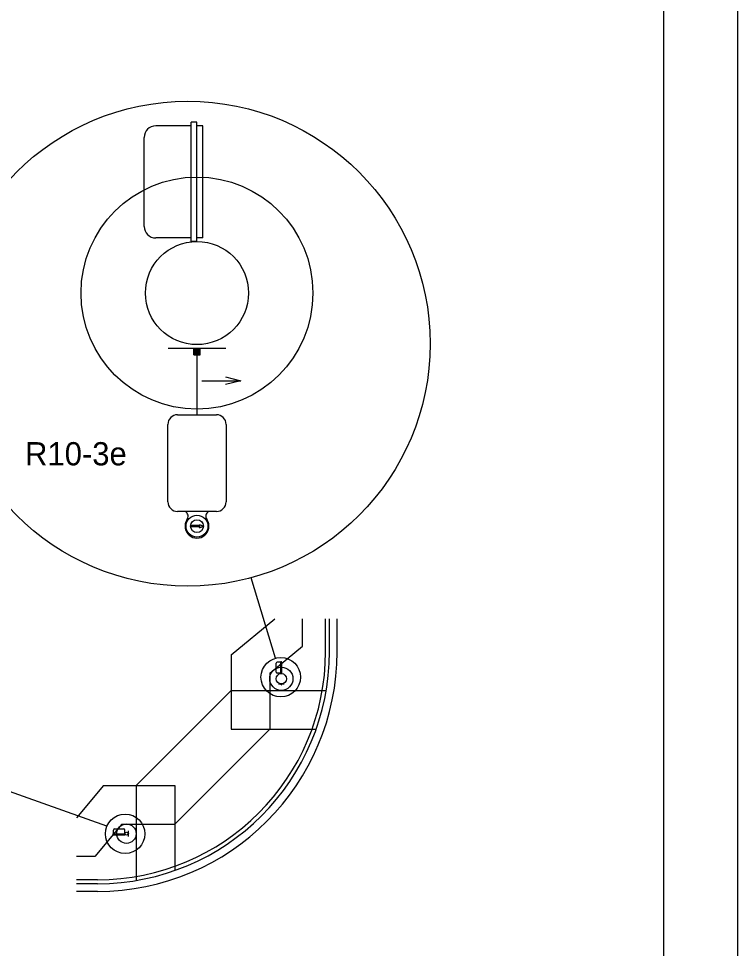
# Model space of a CAD drawing. Extents: x 1369885 to 1370886, y 379976 to 380616.
# Drawn here: x 1370746 to 1370885.5, y 380081.9 to 380262.3 of the extents above; entities that cross this region are included whole.
import ezdxf

# ---------------------------------------------------------------- set-up
doc = ezdxf.new("R2010")
doc.units = 0
for name, color, linetype in [('R_Border', 7, 'Continuous'), ('R_No Plot', 7, 'Continuous'), ('T_Drafting', 7, 'Continuous')]:
    doc.layers.add(name, color=color, linetype=linetype)

msp = doc.modelspace()

# ---------------------------------------------------------------- linework, layer by layer
at = {"layer": 'R_Border'}
msp.add_line((1370871.25, 379987.52), (1370871.25, 380603.9), dxfattribs=at)
at = {"layer": 'R_No Plot'}
msp.add_lwpolyline([(1369885.49, 380615.59), (1370885.51, 380615.59), (1370885.51, 379975.58), (1369885.49, 379975.58)], close=True, dxfattribs=at)
at = {"layer": 'T_Drafting'}
for p, q in [((1370779.52, 380219.04), (1370779.52, 380242.16)), ((1370780.64, 380242.16), (1370779.52, 380242.16)), ((1370780.64, 380219.04), (1370780.64, 380242.16)), ((1370779.52, 380241.48), (1370772.64, 380241.48)), ((1370781.77, 380241.48), (1370780.64, 380241.48)), ((1370781.77, 380219.73), (1370781.77, 380241.48)), ((1370770.39, 380221.98), (1370770.39, 380239.23)), ((1370779.52, 380219.73), (1370772.64, 380219.73)), ((1370780.64, 380219.04), (1370779.52, 380219.04)), ((1370781.77, 380219.73), (1370780.64, 380219.73)), ((1370786.27, 380198.29), (1370775.02, 380198.29)), ((1370780.02, 380197.04), (1370780.02, 380198.29)), ((1370780.02, 380197.05), (1370781.26, 380198.29)), ((1370780.02, 380197.07), (1370781.24, 380198.29)), ((1370780.02, 380197.09), (1370781.22, 380198.29)), ((1370780.02, 380197.11), (1370781.19, 380198.29)), ((1370780.02, 380197.13), (1370781.17, 380198.29)), ((1370780.02, 380197.15), (1370781.15, 380198.29)), ((1370780.02, 380197.17), (1370781.13, 380198.29)), ((1370780.02, 380197.2), (1370781.11, 380198.29)), ((1370780.02, 380197.22), (1370781.09, 380198.29)), ((1370780.02, 380197.24), (1370781.07, 380198.29)), ((1370780.02, 380197.26), (1370781.05, 380198.29)), ((1370780.02, 380197.28), (1370781.02, 380198.29)), ((1370780.02, 380197.3), (1370781, 380198.29)), ((1370780.02, 380197.32), (1370780.98, 380198.29)), ((1370780.02, 380197.34), (1370780.96, 380198.29)), ((1370780.02, 380197.37), (1370780.94, 380198.29)), ((1370780.02, 380197.39), (1370780.92, 380198.29)), ((1370780.02, 380197.41), (1370780.9, 380198.29)), ((1370780.02, 380197.43), (1370780.88, 380198.29)), ((1370780.02, 380197.45), (1370780.85, 380198.29)), ((1370780.02, 380197.47), (1370780.83, 380198.29)), ((1370780.02, 380197.49), (1370780.81, 380198.29)), ((1370780.02, 380197.51), (1370780.79, 380198.29)), ((1370780.02, 380197.54), (1370780.77, 380198.29)), ((1370780.02, 380197.56), (1370780.75, 380198.29)), ((1370780.02, 380197.58), (1370780.73, 380198.29)), ((1370780.02, 380197.6), (1370780.71, 380198.29)), ((1370780.02, 380197.62), (1370780.69, 380198.29)), ((1370780.02, 380197.64), (1370780.66, 380198.29)), ((1370780.02, 380197.66), (1370780.64, 380198.29)), ((1370780.02, 380197.68), (1370780.62, 380198.29)), ((1370780.02, 380197.7), (1370780.6, 380198.29)), ((1370780.02, 380197.73), (1370780.58, 380198.29)), ((1370780.02, 380197.75), (1370780.56, 380198.29)), ((1370780.02, 380197.77), (1370780.54, 380198.29)), ((1370780.02, 380197.79), (1370780.52, 380198.29)), ((1370780.02, 380197.81), (1370780.49, 380198.29)), ((1370780.02, 380197.83), (1370780.47, 380198.29)), ((1370780.02, 380197.85), (1370780.45, 380198.29)), ((1370780.02, 380197.87), (1370780.43, 380198.29)), ((1370780.02, 380197.9), (1370780.41, 380198.29)), ((1370780.02, 380197.92), (1370780.39, 380198.29)), ((1370780.02, 380197.94), (1370780.37, 380198.29)), ((1370780.02, 380197.96), (1370780.35, 380198.29)), ((1370780.02, 380197.98), (1370780.32, 380198.29)), ((1370780.02, 380198), (1370780.3, 380198.29)), ((1370780.02, 380198.02), (1370780.28, 380198.29)), ((1370780.02, 380198.04), (1370780.26, 380198.29)), ((1370780.02, 380198.07), (1370780.24, 380198.29)), ((1370780.02, 380198.09), (1370780.22, 380198.29)), ((1370780.02, 380198.11), (1370780.2, 380198.29)), ((1370780.02, 380198.13), (1370780.18, 380198.29)), ((1370780.02, 380198.15), (1370780.15, 380198.29)), ((1370780.02, 380198.17), (1370780.13, 380198.29)), ((1370780.02, 380198.19), (1370780.11, 380198.29)), ((1370780.02, 380198.21), (1370780.09, 380198.29)), ((1370780.02, 380198.24), (1370780.07, 380198.29)), ((1370780.02, 380198.26), (1370780.05, 380198.29)), ((1370780.02, 380198.28), (1370780.03, 380198.29)), ((1370780.02, 380197.04), (1370781.27, 380197.04)), ((1370780.03, 380197.04), (1370781.27, 380198.28)), ((1370780.05, 380197.04), (1370781.27, 380198.25)), ((1370780.07, 380197.04), (1370781.27, 380198.23)), ((1370780.09, 380197.04), (1370781.27, 380198.21)), ((1370780.11, 380197.04), (1370781.27, 380198.19)), ((1370780.14, 380197.04), (1370781.27, 380198.17)), ((1370780.16, 380197.04), (1370781.27, 380198.15)), ((1370780.18, 380197.04), (1370781.27, 380198.13)), ((1370780.2, 380197.04), (1370781.27, 380198.11)), ((1370780.22, 380197.04), (1370781.27, 380198.09)), ((1370780.24, 380197.04), (1370781.27, 380198.06)), ((1370780.26, 380197.04), (1370781.27, 380198.04)), ((1370780.28, 380197.04), (1370781.27, 380198.02)), ((1370780.3, 380197.04), (1370781.27, 380198)), ((1370780.33, 380197.04), (1370781.27, 380197.98)), ((1370780.35, 380197.04), (1370781.27, 380197.96)), ((1370780.37, 380197.04), (1370781.27, 380197.94)), ((1370780.39, 380197.04), (1370781.27, 380197.92)), ((1370780.41, 380197.04), (1370781.27, 380197.89)), ((1370780.43, 380197.04), (1370781.27, 380197.87)), ((1370780.45, 380197.04), (1370781.27, 380197.85)), ((1370780.47, 380197.04), (1370781.27, 380197.83)), ((1370780.5, 380197.04), (1370781.27, 380197.81)), ((1370780.52, 380197.04), (1370781.27, 380197.79)), ((1370780.54, 380197.04), (1370781.27, 380197.77)), ((1370780.56, 380197.04), (1370781.27, 380197.75)), ((1370780.58, 380197.04), (1370781.27, 380197.72)), ((1370780.6, 380197.04), (1370781.27, 380197.7)), ((1370780.62, 380197.04), (1370781.27, 380197.68)), ((1370780.64, 380197.04), (1370781.27, 380197.66)), ((1370780.64, 380197.04), (1370780.64, 380185.43)), ((1370780.67, 380197.04), (1370781.27, 380197.64)), ((1370780.69, 380197.04), (1370781.27, 380197.62)), ((1370780.71, 380197.04), (1370781.27, 380197.6)), ((1370780.73, 380197.04), (1370781.27, 380197.58)), ((1370780.75, 380197.04), (1370781.27, 380197.55)), ((1370780.77, 380197.04), (1370781.27, 380197.53)), ((1370780.79, 380197.04), (1370781.27, 380197.51)), ((1370780.81, 380197.04), (1370781.27, 380197.49)), ((1370780.84, 380197.04), (1370781.27, 380197.47)), ((1370780.86, 380197.04), (1370781.27, 380197.45)), ((1370780.88, 380197.04), (1370781.27, 380197.43)), ((1370780.9, 380197.04), (1370781.27, 380197.41)), ((1370780.92, 380197.04), (1370781.27, 380197.38)), ((1370780.94, 380197.04), (1370781.27, 380197.36)), ((1370780.96, 380197.04), (1370781.27, 380197.34)), ((1370780.98, 380197.04), (1370781.27, 380197.32)), ((1370781, 380197.04), (1370781.27, 380197.3)), ((1370781.03, 380197.04), (1370781.27, 380197.28)), ((1370781.05, 380197.04), (1370781.27, 380197.26)), ((1370781.07, 380197.04), (1370781.27, 380197.24)), ((1370781.09, 380197.04), (1370781.27, 380197.22)), ((1370781.11, 380197.04), (1370781.27, 380197.19)), ((1370781.13, 380197.04), (1370781.27, 380197.17)), ((1370781.15, 380197.04), (1370781.27, 380197.15)), ((1370781.17, 380197.04), (1370781.27, 380197.13)), ((1370781.2, 380197.04), (1370781.27, 380197.11)), ((1370781.22, 380197.04), (1370781.27, 380197.09)), ((1370781.24, 380197.04), (1370781.27, 380197.07)), ((1370781.26, 380197.04), (1370781.27, 380197.05)), ((1370781.27, 380197.04), (1370781.27, 380198.29)), ((1370781.61, 380192.04), (1370789.16, 380192.04)), ((1370776.87, 380185.43), (1370784.42, 380185.43)), ((1370774.99, 380168.56), (1370774.99, 380183.56)), ((1370786.29, 380183.56), (1370786.29, 380168.56)), ((1370784.42, 380166.68), (1370776.87, 380166.68)), ((1370779.4, 380163.95), (1370779.4, 380163.72)), ((1370781.28, 380163.95), (1370779.4, 380163.95)), ((1370781.28, 380163.72), (1370779.4, 380163.72)), ((1370781.13, 380164.13), (1370781.89, 380163.83)), ((1370781.28, 380163.95), (1370781.13, 380164.13)), ((1370781.13, 380163.53), (1370781.89, 380163.83)), ((1370781.13, 380163.53), (1370781.28, 380163.72)), ((1370795.86, 380138.21), (1370791.16, 380153.82)), ((1370787.26, 380138.87), (1370795.72, 380145.82)), ((1370801.09, 380140.53), (1370801.09, 380145.82)), ((1370805.59, 380139.48), (1370805.59, 380145.82)), ((1370806.34, 380139.48), (1370806.34, 380145.82)), ((1370807.84, 380139.48), (1370807.84, 380145.82)), ((1370794.76, 380135.33), (1370801.09, 380140.53)), ((1370787.26, 380138.87), (1370787.26, 380124.48)), ((1370795.99, 380135.52), (1370795.99, 380137.25)), ((1370796.9, 380137.47), (1370796.21, 380137.47)), ((1370796.9, 380135.23), (1370796.9, 380137.54)), ((1370797.01, 380137.54), (1370796.9, 380137.54)), ((1370797.01, 380135.23), (1370797.01, 380137.54)), ((1370797.12, 380137.47), (1370797.01, 380137.47)), ((1370797.12, 380135.3), (1370797.12, 380137.47)), ((1370794.76, 380135.33), (1370794.76, 380124.48)), ((1370796.9, 380135.3), (1370796.21, 380135.3)), ((1370797.01, 380135.23), (1370796.9, 380135.23)), ((1370797.12, 380135.3), (1370797.01, 380135.3)), ((1370787.26, 380131.98), (1370768.84, 380113.55)), ((1370787.26, 380131.98), (1370805.71, 380131.98)), ((1370797.57, 380133.15), (1370796.45, 380133.15)), ((1370796.95, 380133.03), (1370796.95, 380133.15)), ((1370796.95, 380133.03), (1370797.07, 380133.15)), ((1370796.95, 380133.03), (1370797.07, 380133.15)), ((1370796.95, 380133.03), (1370797.07, 380133.15)), ((1370796.95, 380133.03), (1370797.07, 380133.15)), ((1370796.95, 380133.03), (1370797.07, 380133.15)), ((1370796.95, 380133.04), (1370797.07, 380133.15)), ((1370796.95, 380133.04), (1370797.07, 380133.15)), ((1370796.95, 380133.04), (1370797.06, 380133.15)), ((1370796.95, 380133.04), (1370797.06, 380133.15)), ((1370796.95, 380133.05), (1370797.06, 380133.15)), ((1370796.95, 380133.05), (1370797.06, 380133.15)), ((1370796.95, 380133.05), (1370797.05, 380133.15)), ((1370796.95, 380133.05), (1370797.05, 380133.15)), ((1370796.95, 380133.05), (1370797.05, 380133.15)), ((1370796.95, 380133.06), (1370797.05, 380133.15)), ((1370796.95, 380133.06), (1370797.05, 380133.15)), ((1370796.95, 380133.06), (1370797.04, 380133.15)), ((1370796.95, 380133.06), (1370797.04, 380133.15)), ((1370796.95, 380133.06), (1370797.04, 380133.15)), ((1370796.95, 380133.07), (1370797.04, 380133.15)), ((1370796.95, 380133.07), (1370797.04, 380133.15)), ((1370796.95, 380133.07), (1370797.03, 380133.15)), ((1370796.95, 380133.07), (1370797.03, 380133.15)), ((1370796.95, 380133.07), (1370797.03, 380133.15)), ((1370796.95, 380133.08), (1370797.03, 380133.15)), ((1370796.95, 380133.08), (1370797.03, 380133.15)), ((1370796.95, 380133.08), (1370797.02, 380133.15)), ((1370796.95, 380133.08), (1370797.02, 380133.15)), ((1370796.95, 380133.09), (1370797.02, 380133.15)), ((1370796.95, 380133.09), (1370797.02, 380133.15)), ((1370796.95, 380133.09), (1370797.01, 380133.15)), ((1370796.95, 380133.09), (1370797.01, 380133.15)), ((1370796.95, 380133.09), (1370797.01, 380133.15)), ((1370796.95, 380133.1), (1370797.01, 380133.15)), ((1370796.95, 380133.1), (1370797.01, 380133.15)), ((1370796.95, 380133.1), (1370797, 380133.15)), ((1370796.95, 380133.1), (1370797, 380133.15)), ((1370796.95, 380133.1), (1370797, 380133.15)), ((1370796.95, 380133.11), (1370797, 380133.15)), ((1370796.95, 380133.11), (1370797, 380133.15)), ((1370796.95, 380133.11), (1370796.99, 380133.15)), ((1370796.95, 380133.11), (1370796.99, 380133.15)), ((1370796.95, 380133.12), (1370796.99, 380133.15)), ((1370796.95, 380133.12), (1370796.99, 380133.15)), ((1370796.95, 380133.12), (1370796.98, 380133.15)), ((1370796.95, 380133.12), (1370796.98, 380133.15)), ((1370796.95, 380133.12), (1370796.98, 380133.15)), ((1370796.95, 380133.13), (1370796.98, 380133.15)), ((1370796.95, 380133.13), (1370796.98, 380133.15)), ((1370796.95, 380133.13), (1370796.97, 380133.15)), ((1370796.95, 380133.13), (1370796.97, 380133.15)), ((1370796.95, 380133.13), (1370796.97, 380133.15)), ((1370796.95, 380133.14), (1370796.97, 380133.15)), ((1370796.95, 380133.14), (1370796.97, 380133.15)), ((1370796.95, 380133.14), (1370796.96, 380133.15)), ((1370796.95, 380133.14), (1370796.96, 380133.15)), ((1370796.95, 380133.14), (1370796.96, 380133.15)), ((1370796.95, 380133.15), (1370796.96, 380133.15)), ((1370796.95, 380133.15), (1370796.96, 380133.15)), ((1370796.95, 380133.15), (1370796.95, 380133.15)), ((1370796.95, 380133.15), (1370796.95, 380133.15)), ((1370796.95, 380133.03), (1370797.07, 380133.03)), ((1370796.96, 380133.03), (1370797.07, 380133.15)), ((1370796.96, 380133.03), (1370797.07, 380133.15)), ((1370796.96, 380133.03), (1370797.07, 380133.14)), ((1370796.96, 380133.03), (1370797.07, 380133.14)), ((1370796.96, 380133.03), (1370797.07, 380133.14)), ((1370796.97, 380133.03), (1370797.07, 380133.14)), ((1370796.97, 380133.03), (1370797.07, 380133.14)), ((1370796.97, 380133.03), (1370797.07, 380133.13)), ((1370796.97, 380133.03), (1370797.07, 380133.13)), ((1370796.97, 380133.03), (1370797.07, 380133.13)), ((1370796.98, 380133.03), (1370797.07, 380133.13)), ((1370796.98, 380133.03), (1370797.07, 380133.13)), ((1370796.98, 380133.03), (1370797.07, 380133.12)), ((1370796.98, 380133.03), (1370797.07, 380133.12)), ((1370796.99, 380133.03), (1370797.07, 380133.12)), ((1370796.99, 380133.03), (1370797.07, 380133.12)), ((1370796.99, 380133.03), (1370797.07, 380133.11)), ((1370796.99, 380133.03), (1370797.07, 380133.11)), ((1370796.99, 380133.03), (1370797.07, 380133.11)), ((1370797, 380133.03), (1370797.07, 380133.11)), ((1370797, 380133.03), (1370797.07, 380133.11)), ((1370797, 380133.03), (1370797.07, 380133.1)), ((1370797, 380133.03), (1370797.07, 380133.1)), ((1370797, 380133.03), (1370797.07, 380133.1)), ((1370797.01, 380133.03), (1370797.07, 380133.1)), ((1370797.01, 380133.03), (1370797.07, 380133.1)), ((1370797.01, 380133.03), (1370797.07, 380133.09)), ((1370797.01, 380133.03), (1370797.07, 380133.09)), ((1370797.01, 380133.03), (1370797.07, 380133.09)), ((1370797.02, 380133.03), (1370797.07, 380133.09)), ((1370797.02, 380133.03), (1370797.07, 380133.09)), ((1370797.02, 380133.03), (1370797.07, 380133.08)), ((1370797.02, 380133.03), (1370797.07, 380133.08)), ((1370797.03, 380133.03), (1370797.07, 380133.08)), ((1370797.03, 380133.03), (1370797.07, 380133.08)), ((1370797.03, 380133.03), (1370797.07, 380133.07)), ((1370797.03, 380133.03), (1370797.07, 380133.07)), ((1370797.03, 380133.03), (1370797.07, 380133.07)), ((1370797.04, 380133.03), (1370797.07, 380133.07)), ((1370797.04, 380133.03), (1370797.07, 380133.07)), ((1370797.04, 380133.03), (1370797.07, 380133.06)), ((1370797.04, 380133.03), (1370797.07, 380133.06)), ((1370797.04, 380133.03), (1370797.07, 380133.06)), ((1370797.05, 380133.03), (1370797.07, 380133.06)), ((1370797.05, 380133.03), (1370797.07, 380133.06)), ((1370797.05, 380133.03), (1370797.07, 380133.05)), ((1370797.05, 380133.03), (1370797.07, 380133.05)), ((1370797.06, 380133.03), (1370797.07, 380133.05)), ((1370797.06, 380133.03), (1370797.07, 380133.05)), ((1370797.06, 380133.03), (1370797.07, 380133.04)), ((1370797.06, 380133.03), (1370797.07, 380133.04)), ((1370797.06, 380133.03), (1370797.07, 380133.04)), ((1370797.07, 380133.03), (1370797.07, 380133.15)), ((1370797.07, 380133.03), (1370797.07, 380133.04)), ((1370797.07, 380133.03), (1370797.07, 380133.04)), ((1370797.07, 380133.03), (1370797.07, 380133.03)), ((1370797.07, 380133.03), (1370797.07, 380133.03)), ((1370797.07, 380133.03), (1370797.07, 380133.03)), ((1370794.76, 380124.48), (1370776.34, 380106.05)), ((1370787.26, 380124.48), (1370803.76, 380124.48)), ((1370763.17, 380105.63), (1370742.21, 380113.09)), ((1370762.5, 380113.55), (1370757.29, 380107.23)), ((1370762.5, 380113.55), (1370776.34, 380113.55)), ((1370768.84, 380113.55), (1370768.84, 380095.11)), ((1370776.34, 380113.55), (1370776.34, 380097.05)), ((1370766.04, 380106.05), (1370760.84, 380099.73)), ((1370764.44, 380104.18), (1370764.44, 380104.87)), ((1370764.66, 380105.09), (1370766.39, 380105.09)), ((1370766.04, 380106.05), (1370776.34, 380106.05)), ((1370766.61, 380104.18), (1370766.61, 380104.87)), ((1370767.32, 380104.74), (1370767.32, 380103.62)), ((1370764.37, 380104.18), (1370766.68, 380104.18)), ((1370764.37, 380104.07), (1370764.37, 380104.18)), ((1370764.37, 380104.07), (1370766.68, 380104.07)), ((1370764.44, 380103.95), (1370764.44, 380104.07)), ((1370764.44, 380103.95), (1370766.61, 380103.95)), ((1370766.61, 380103.95), (1370766.61, 380104.07)), ((1370766.68, 380104.07), (1370766.68, 380104.18)), ((1370767.44, 380104.24), (1370767.32, 380104.24)), ((1370767.32, 380104.12), (1370767.44, 380104.24)), ((1370767.32, 380104.12), (1370767.44, 380104.24)), ((1370767.32, 380104.12), (1370767.44, 380104.24)), ((1370767.32, 380104.12), (1370767.44, 380104.24)), ((1370767.32, 380104.12), (1370767.44, 380104.24)), ((1370767.32, 380104.12), (1370767.44, 380104.24)), ((1370767.32, 380104.12), (1370767.43, 380104.24)), ((1370767.32, 380104.13), (1370767.43, 380104.24)), ((1370767.32, 380104.13), (1370767.43, 380104.24)), ((1370767.32, 380104.13), (1370767.43, 380104.24)), ((1370767.32, 380104.13), (1370767.42, 380104.24)), ((1370767.32, 380104.13), (1370767.42, 380104.24)), ((1370767.32, 380104.14), (1370767.42, 380104.24)), ((1370767.32, 380104.14), (1370767.42, 380104.24)), ((1370767.32, 380104.14), (1370767.42, 380104.24)), ((1370767.32, 380104.14), (1370767.41, 380104.24)), ((1370767.32, 380104.15), (1370767.41, 380104.24)), ((1370767.32, 380104.15), (1370767.41, 380104.24)), ((1370767.32, 380104.15), (1370767.41, 380104.24)), ((1370767.32, 380104.15), (1370767.41, 380104.24)), ((1370767.32, 380104.15), (1370767.4, 380104.24)), ((1370767.32, 380104.16), (1370767.4, 380104.24)), ((1370767.32, 380104.16), (1370767.4, 380104.24)), ((1370767.32, 380104.16), (1370767.4, 380104.24)), ((1370767.32, 380104.16), (1370767.4, 380104.24)), ((1370767.32, 380104.16), (1370767.39, 380104.24)), ((1370767.32, 380104.17), (1370767.39, 380104.24)), ((1370767.32, 380104.17), (1370767.39, 380104.24)), ((1370767.32, 380104.17), (1370767.39, 380104.24)), ((1370767.32, 380104.17), (1370767.38, 380104.24)), ((1370767.32, 380104.18), (1370767.38, 380104.24)), ((1370767.32, 380104.18), (1370767.38, 380104.24)), ((1370767.32, 380104.18), (1370767.38, 380104.24)), ((1370767.32, 380104.18), (1370767.38, 380104.24)), ((1370767.32, 380104.18), (1370767.37, 380104.24)), ((1370767.32, 380104.19), (1370767.37, 380104.24)), ((1370767.32, 380104.19), (1370767.37, 380104.24)), ((1370767.32, 380104.19), (1370767.37, 380104.24)), ((1370767.32, 380104.19), (1370767.37, 380104.24)), ((1370767.32, 380104.19), (1370767.36, 380104.24)), ((1370767.32, 380104.2), (1370767.36, 380104.24)), ((1370767.32, 380104.2), (1370767.36, 380104.24)), ((1370767.32, 380104.2), (1370767.36, 380104.24)), ((1370767.32, 380104.2), (1370767.35, 380104.24)), ((1370767.32, 380104.2), (1370767.35, 380104.24)), ((1370767.32, 380104.21), (1370767.35, 380104.24)), ((1370767.32, 380104.21), (1370767.35, 380104.24)), ((1370767.32, 380104.21), (1370767.35, 380104.24)), ((1370767.32, 380104.21), (1370767.34, 380104.24)), ((1370767.32, 380104.22), (1370767.34, 380104.24)), ((1370767.32, 380104.22), (1370767.34, 380104.24)), ((1370767.32, 380104.22), (1370767.34, 380104.24)), ((1370767.32, 380104.22), (1370767.34, 380104.24)), ((1370767.32, 380104.22), (1370767.33, 380104.24)), ((1370767.32, 380104.23), (1370767.33, 380104.24)), ((1370767.32, 380104.23), (1370767.33, 380104.24)), ((1370767.32, 380104.23), (1370767.33, 380104.24)), ((1370767.32, 380104.23), (1370767.33, 380104.24)), ((1370767.32, 380104.23), (1370767.32, 380104.24)), ((1370767.32, 380104.24), (1370767.32, 380104.24)), ((1370767.32, 380104.24), (1370767.32, 380104.24)), ((1370767.32, 380104.12), (1370767.44, 380104.23)), ((1370767.44, 380104.12), (1370767.32, 380104.12)), ((1370767.33, 380104.12), (1370767.44, 380104.23)), ((1370767.33, 380104.12), (1370767.44, 380104.23)), ((1370767.33, 380104.12), (1370767.44, 380104.23)), ((1370767.33, 380104.12), (1370767.44, 380104.23)), ((1370767.33, 380104.12), (1370767.44, 380104.22)), ((1370767.34, 380104.12), (1370767.44, 380104.22)), ((1370767.34, 380104.12), (1370767.44, 380104.22)), ((1370767.34, 380104.12), (1370767.44, 380104.22)), ((1370767.34, 380104.12), (1370767.44, 380104.22)), ((1370767.34, 380104.12), (1370767.44, 380104.21)), ((1370767.35, 380104.12), (1370767.44, 380104.21)), ((1370767.35, 380104.12), (1370767.44, 380104.21)), ((1370767.35, 380104.12), (1370767.44, 380104.21)), ((1370767.35, 380104.12), (1370767.44, 380104.2)), ((1370767.36, 380104.12), (1370767.44, 380104.2)), ((1370767.36, 380104.12), (1370767.44, 380104.2)), ((1370767.36, 380104.12), (1370767.44, 380104.2)), ((1370767.36, 380104.12), (1370767.44, 380104.2)), ((1370767.36, 380104.12), (1370767.44, 380104.19)), ((1370767.37, 380104.12), (1370767.44, 380104.19)), ((1370767.37, 380104.12), (1370767.44, 380104.19)), ((1370767.37, 380104.12), (1370767.44, 380104.19)), ((1370767.37, 380104.12), (1370767.44, 380104.19)), ((1370767.37, 380104.12), (1370767.44, 380104.18)), ((1370767.38, 380104.12), (1370767.44, 380104.18)), ((1370767.38, 380104.12), (1370767.44, 380104.18)), ((1370767.38, 380104.12), (1370767.44, 380104.18)), ((1370767.38, 380104.12), (1370767.44, 380104.18)), ((1370767.38, 380104.12), (1370767.44, 380104.17)), ((1370767.39, 380104.12), (1370767.44, 380104.17)), ((1370767.39, 380104.12), (1370767.44, 380104.17)), ((1370767.39, 380104.12), (1370767.44, 380104.17)), ((1370767.39, 380104.12), (1370767.44, 380104.16)), ((1370767.4, 380104.12), (1370767.44, 380104.16)), ((1370767.4, 380104.12), (1370767.44, 380104.16)), ((1370767.4, 380104.12), (1370767.44, 380104.16)), ((1370767.4, 380104.12), (1370767.44, 380104.16)), ((1370767.4, 380104.12), (1370767.44, 380104.15)), ((1370767.41, 380104.12), (1370767.44, 380104.15)), ((1370767.41, 380104.12), (1370767.44, 380104.15)), ((1370767.41, 380104.12), (1370767.44, 380104.15)), ((1370767.41, 380104.12), (1370767.44, 380104.15)), ((1370767.41, 380104.12), (1370767.44, 380104.14)), ((1370767.42, 380104.12), (1370767.44, 380104.14)), ((1370767.42, 380104.12), (1370767.44, 380104.14)), ((1370767.42, 380104.12), (1370767.44, 380104.14)), ((1370767.42, 380104.12), (1370767.44, 380104.13)), ((1370767.43, 380104.12), (1370767.44, 380104.13)), ((1370767.43, 380104.12), (1370767.44, 380104.13)), ((1370767.43, 380104.12), (1370767.44, 380104.13)), ((1370767.43, 380104.12), (1370767.44, 380104.13)), ((1370767.43, 380104.12), (1370767.44, 380104.12)), ((1370767.44, 380104.12), (1370767.44, 380104.24)), ((1370767.44, 380104.12), (1370767.44, 380104.12)), ((1370767.44, 380104.12), (1370767.44, 380104.12)), ((1370767.44, 380104.12), (1370767.44, 380104.12)), ((1370767.44, 380104.12), (1370767.44, 380104.12)), ((1370760.84, 380099.73), (1370757.29, 380099.73)), ((1370761.34, 380095.23), (1370757.29, 380095.23)), ((1370761.34, 380094.48), (1370757.29, 380094.48)), ((1370761.34, 380092.98), (1370757.29, 380092.98))]:
    msp.add_line(p, q, dxfattribs=at)
msp.add_lwpolyline([(1370786.16, 380192.79), (1370789.16, 380192.04), (1370786.16, 380191.29)], dxfattribs=at)
for centre, radius in [((1370778.86, 380199.21), 47.03), ((1370780.64, 380209.04), 22.5), ((1370780.64, 380209.04), 10), ((1370780.64, 380163.83), 2.12), ((1370780.64, 380163.83), 1.25), ((1370796.89, 380134.52), 3.83), ((1370797.01, 380134.23), 2.25), ((1370797.01, 380134.23), 1), ((1370766.7, 380104.16), 3.83), ((1370766.96, 380104.18), 1.88), ((1370766.96, 380104.18), 0.281)]:
    msp.add_circle(centre, radius, dxfattribs=at)
for centre, radius, start, end in [((1370772.64, 380239.23), 2.25, 90, 180), ((1370772.64, 380221.98), 2.25, 180, 270), ((1370776.87, 380183.56), 1.88, 90, 180), ((1370784.42, 380183.56), 1.88, 0, 90), ((1370776.87, 380168.56), 1.88, 180, 270), ((1370784.42, 380168.56), 1.88, 270, 0), ((1370777.88, 380165.73), 1.05, 318.1972, 64.8044), ((1370783.4, 380165.73), 1.05, 115.1956, 221.8028), ((1370780.64, 380163.83), 2.31, 148.7402, 227.4934), ((1370780.64, 380163.83), 2.31, 148.7402, 31.2598), ((1370780.64, 380163.83), 2.31, 312.5066, 31.2598), ((1370761.34, 380139.48), 45, 270, 0), ((1370761.34, 380139.48), 46.5, 270, 0), ((1370761.34, 380139.48), 44.25, 270, 0), ((1370796.21, 380137.25), 0.225, 90, 180), ((1370796.21, 380135.52), 0.225, 180, 270), ((1370764.66, 380104.87), 0.225, 90, 180), ((1370766.39, 380104.87), 0.225, 360, 90)]:
    msp.add_arc(centre, radius, start, end, dxfattribs=at)

# ---------------------------------------------------------------- texts
msp.add_text('R10-3e', height=4.5, dxfattribs=at).set_placement((1370747.28, 380175.62))

doc.saveas('drawing.dxf')
